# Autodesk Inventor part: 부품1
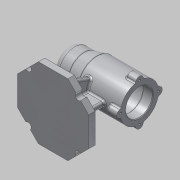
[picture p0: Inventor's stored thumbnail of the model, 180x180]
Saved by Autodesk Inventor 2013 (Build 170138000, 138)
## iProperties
Created: 2019-12
Part Number: 부품1
Material: 알루미늄 6061
Document SubType Name: Modeling
Designer: Administrator
Density: 2.71 g/cm^3
Mass: 728.649 g
Surface Area: 713.108 cm^2
Volume: 268.874 cm^3
Author: Administrator
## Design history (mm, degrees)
sketch "스케치5"
  geometry: L1 (0, 0)-(42.956, 0); L2 (0, 25)-(25, 25); L3 (25, 25)-(45, 30); L4 (45, 30)-(112, 30); L5 (112, 30)-(112, 21); L6 (112, 21)-(97, 21); L7 (97, 21)-(97, 24); L8 (97, 24)-(43, 24); L9 (43, 24)-(43, 21); L10 (43, 21)-(31, 21); L11 (31, 21)-(31, 17.5); L12 (31, 17.5)-(13, 17.5); L13 (13, 17.5)-(13, 16); L14 (13, 16)-(9, 16); L15 (9, 16)-(9, 10.5); L16 (0, 25)-(0, 0); L17 (9, 10.5)-(6, 10.5); L18 (6, 10.5)-(6, 0); L19 (0, 0)-(6, 0)
  constraints: 38 end point, 10 parallel, 5 perpendicular, 2 horizontal, 1 collinear, 1 point on line
  dimensions: "d28" = 50 diameter of L2 L1; "d30" = 112 distance between parallel lines of L5 L16; "d31" = 25 distance from line of L2.end L16; "d32" = 45 distance from line of L3.end L16; "d33" = 60 diameter of L4 L1; "d34" = 15 distance between parallel lines of L5 L7; "d35" = 42 diameter of L6 L1; "d36" = 54 distance between parallel lines of L7 L9; "d37" = 48 diameter of L8 L1; "d39" = 42 diameter of L10 L1; "d40" = 12 distance between parallel lines of L9 L11; "d41" = 18 distance between parallel lines of L13 L11; "d42" = 35 diameter of L12 L1; "d43" = 4 distance between parallel lines of L13 L15; "d44" = 32 diameter of L14 L1; "d45" = 3 distance between parallel lines of L15 L18; "d46" = 21 diameter of L17 L1
revolve "회전1" sketch "스케치5" stored, may be unused: angle "d47" = 90 deg
node "작업 평면1"
sketch "스케치6"
  geometry: L1 (-79.196, -56)-(-112, -23.196); L2 (-112, -23.196)-(-112, 23.196); L3 (-112, 23.196)-(-79.196, 56); L4 (-79.196, 56)-(-32.804, 56); L5 (-32.804, 56)-(0, 23.196); L6 (0, 23.196)-(0, -23.196); L7 (0, -23.196)-(-32.804, -56); L8 (-32.804, -56)-(-79.196, -56); L9 (-56, 0)-(-16.402, -39.598); L10 (0, 0)-(-56, 0); L11 (-56, 0)-(-16.402, 39.598); C1 r 56 at (-56, 0); 2 further points
  constraints: 22 end point, 4 midpoint, 2 horizontal alignment, 1 centre point, 1 coincident, 1 parallel, 1 perpendicular, 1 tangent, 1 vertical, 17 other
  dimensions: "d49" = 112 diameter of C1; "d51" = 45 deg angle of L10 L9
extrude "돌출1" join sketch "스케치6" distance "d53" = 10; taper "d54" = 0 deg
sketch "스케치7"
  geometry: L1 (79.196, 56)-(32.804, 56) reference; L2 (32.804, -56)-(79.196, -56) reference; L3 (112, -23.196)-(112, 23.196) reference; L4 (0, 23.196)-(32.804, 56) reference; L5 (0, 0)-(112, 0); L6 (56, 56)-(56, -56); L7 (56, 0)-(16.402, 39.598); C1 r 5 at (16.402, 39.598); C2 r 5 at (16.402, -39.598); C3 r 5 at (95.598, -39.598); C4 r 5 at (95.598, 39.598)
  constraints: 6 end point, 5 midpoint, 4 centre point, 1 perpendicular, 9 other
  dimensions: "d55" = 10 diameter of C1; "d61" = 360 deg dimension on L7.start L7.end (derived)
extrude "돌출2" cut sketch "스케치7" distance "d57" = 10; taper "d58" = 0 deg
sketch "스케치8"
  geometry: L1 (112, -23.196)-(112, 23.196) reference; L2 (0, 23.196)-(0, -23.196) reference; L3 (52, 4)-(87, 4); L4 (87, 4)-(87, -4); L5 (87, -4)-(52, -4); L6 (52, -4)-(52, 4); 3 further points
  constraints: 8 end point, 2 midpoint, 2 parallel, 1 horizontal, 1 horizontal alignment, 1 perpendicular
  dimensions: "d63" = 8 distance between parallel lines of L3 L5; "d65" = 25 distance between parallel lines of L1 L4; "d66" = 60 distance between parallel lines of L1 L6
extrude "돌출3" join sketch "스케치8" stored distance "d67" = 10; taper "d68" = 0 deg
node "작업 평면2"
sketch "스케치9"
  geometry: L1 (-10, -59.196)-(-56.766, -42.174); L2 (0, -79.196)-(-10, -79.196) reference; L3 (-10, -66.329)-(-10, -79.196) reference; 2 further points
  constraints: 2 end point, 1 point on line, 2 other
  dimensions: "d70" = 110 deg angle of L1 L3; "d71" = 20 distance from line of L1.start L2
feature "리브1" sketch "스케치9" dims "d72" = 1, "d73" = 8, "d74" = 0, "d75" = 0, "d76" = 1, "d77" = 1
node "작업 평면3"
sketch "스케치10"
  geometry: L1 (54.196, 55)-(34.196, 50) reference; L2 (41.672, 51.869)-(61.196, 10); L3 (57.794, 10)-(66.329, 10) reference; L4 (79.196, 0)-(79.196, 10) reference; L5 (79.196, 10)-(66.329, 10) reference; 2 further points
  constraints: 2 end point, 2 point on line
  dimensions: "d78" = 18 distance from line of L4 L2.end; "d79" = 115 deg angle of L5 L2
feature "리브2" sketch "스케치10" dims "d80" = 1, "d81" = 8, "d82" = 0, "d83" = 0, "d84" = 1, "d85" = 1
sketch "스케치11"
  geometry: C1 r 6 at (0, 30); C2 r 6 at (-30, 0); C3 r 6 at (0, -30); C4 r 6 at (30, 0); 1 further point
  constraints: 4 centre point, 2 vertical alignment, 10 other
  dimensions: "d86" = 12 diameter of C1; "d91" = 360 deg dimension on point (0, 0) C1.centre (derived)
extrude "돌출4" join sketch "스케치11" distance "d93" = 16; taper "d94" = 0 deg
sketch "스케치12"
  geometry: A1 r 6 centre (30, 30) between (35.97, 29.4) and (24.03, 29.4) reference; A2 r 6 centre (0, 0) between (0.6, 5.97) and (0.6, -5.97) reference; A3 r 6 centre (30, -30) between (24.03, -29.4) and (35.97, -29.4) reference; A4 r 6 centre (60, 0) between (59.4, -5.97) and (59.4, 5.97) reference
hole "구멍1" sketch "스케치12" at (30, 30), (0, 0), (30, -30), (60, 0) diameter "d95" = 3.242; stored, may be unused: countersink angle "d99" = 90 deg, drill point angle "d101" = 118 deg; dims "d96" = 8, "d97" = 4, "d98" = 2, "d100" = 11
fillet "모깎기1" dims "d102" = 3, "d103" = 0.3
chamfer "모따기1" distance "d104" = 1; stored, may be unused: second distance "d105" = 2, angle "d106" = 45 deg
fillet "모깎기2" dims "d107" = 3, "d108" = 10, "d109" = 1
fillet "모깎기3" dims "d110" = 3
node "솔리드1"
mirror "대칭1"
